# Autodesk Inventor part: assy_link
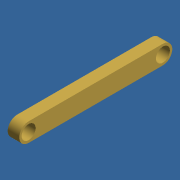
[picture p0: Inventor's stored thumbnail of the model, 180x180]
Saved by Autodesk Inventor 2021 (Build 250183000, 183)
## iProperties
Manager: Dave Ford
Company: Autodesk Inc.
Shininess: 0.0
Length Units: 11269
Angle Units: 11279
Time Units: 11290
Mass Units: 11284
Length Display Precision: 1
Angle Display Precision: 2
Compacted: True
Created: 2000-03
Part Number: assy_link
Document SubType Name: Modeling
Designer: Peter Roberts
Density: 1 g/cm^3
Material: Generic
Mass: 2.32516 g
Surface Area: 18.395 cm^2
Volume: 2.32516 cm^3
Appearance: Default
Density: 8.47
Volumn: 3.4791185596282106
Area: 22.101520402215122
PropertySet Name: Model Information
Control State: 0
Checked Out: False
Master: False
Title: Valve Linkage
Subject: Tutorial #4 reference file
Author: Peter Roberts
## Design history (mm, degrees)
node "Extrusion1" dims "d4" = 4.95, "d5" = 0
  sketch "Sketch1"
    geometry: L1 (0, 4)-(57.5, 4); L2 (57.5, -4)-(0, -4); C1 r 3 at (0, 0); C2 r 3 at (57.5, 0); A1 r 4 centre (57.5, 0) between (57.5, -4) and (57.5, 4); A2 r 4 centre (0, 0) between (0, 4) and (0, -4); 1 further point
    constraints: 4 centre point, 4 end point, 4 point on circle, 4 tangent, 3 coincident, 1 horizontal alignment
    dimensions: "d0" = 4 radius of A1; "d1" = 6 diameter of C2; "d2" = 4 radius of A2; "d3" = 6 diameter of C1; "d6" = 57.5 distance of A1.centre A2.centre
body "Solid1"
